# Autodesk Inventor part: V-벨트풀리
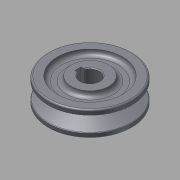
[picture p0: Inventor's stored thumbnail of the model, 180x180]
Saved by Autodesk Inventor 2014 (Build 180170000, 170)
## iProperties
Created: 2015-12
Part Number: V-벨트풀리
Material: 강철, 연강
Document SubType Name: Modeling
Designer: mdu
Density: 7.86 g/cm^3
Appearance: 강철
CustomPartVersion: 1
Author: mdu
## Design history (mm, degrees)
sketch "주 스케치"
  geometry: L1 (0, 16)-(27, 16); L2 (27, 16)-(27, 12.861); L3 (27, 12.861)-(16, 9.498); L4 (16, 9.498)-(16, 6.502); L5 (16, 6.502)-(27, 3.139); L6 (27, 3.139)-(27, 0); L7 (27, 0)-(0, 0); L8 (25, 12.25)-(25, 3.75); L9 (16, 8)-(25, 8); L10 (27, 12.861)-(27, 3.139); L11 (0, -3)-(0, 18) reference; L12 (0, 0)-(0, 16)
  constraints: 22 end point, 5 perpendicular, 2 collinear, 2 midpoint, 2 point on line, 1 parallel
  dimensions: "d0" = 8.5 distance of L8.start L8.end (= da_Bw); "d1" = 34 deg angle of L3 L5 (= da_Alfa); "d2" = 2 distance between parallel lines of L2 L8 (= da_c); "d6" = 16 distance between parallel lines of L7 L1 (computed from d5, da_ng, da_Sg); "d21" = 50 diameter of L8 L11 (= da_Dw); "d25" = 11 distance between parallel lines of L4 L10 (= da_Hd); "d27" = 8 distance between parallel lines of L7 L9 (= da_Se)
node "벨트 평면"
revolve "본체" stored, may be unused: angle "d7" = 90 deg
revolve "그루브" stored, may be unused: angle "d15" = 90 deg
feature "허브 키홈"
fillet "모깎기3" dims "d28" = 0.5, "d29" = 1, "d30" = 1
sketch "스케치2"
  geometry: C1 r 12 at (0, 0); C2 r 21 at (0, 0); 1 further point
  constraints: 2 centre point, 2 coincident
  dimensions: "d31" = 24 diameter of C1; "d32" = 42 diameter of C2
extrude "돌출1" cut sketch "스케치2" distance "d33" = 3; taper "d34" = 0 deg
fillet "모깎기4" dims "d35" = 3
node "작업 평면2"
chamfer "모따기1" distance "d36" = 0.5; stored, may be unused: second distance "d37" = 2, angle "d38" = 45 deg
body "Solid1"
pattern_linear "그루브 패턴" dims "d18" = 12 (= da_Sg)
mirror "대칭1"
other parameters: "d5" = 8 (= da_Se), "da_Bw" = 8.5 [user parameter; used in 1 equation term], "da_Alfa" = 34 deg [user parameter; used in 1 equation term], "da_c" = 2 [user parameter; used in 1 equation term], "da_Dw" = 50 [user parameter; used in 1 equation term], "da_Hd" = 11 [user parameter; used in 1 equation term], "da_Se" = 8 [user parameter; used in 2 equation terms], "da_Sg" = 12 [user parameter; used in 2 equation terms], "da_r1" = 0 [user parameter], "da_r2" = 0 [user parameter], "d24" = 0, "d26" = 0
